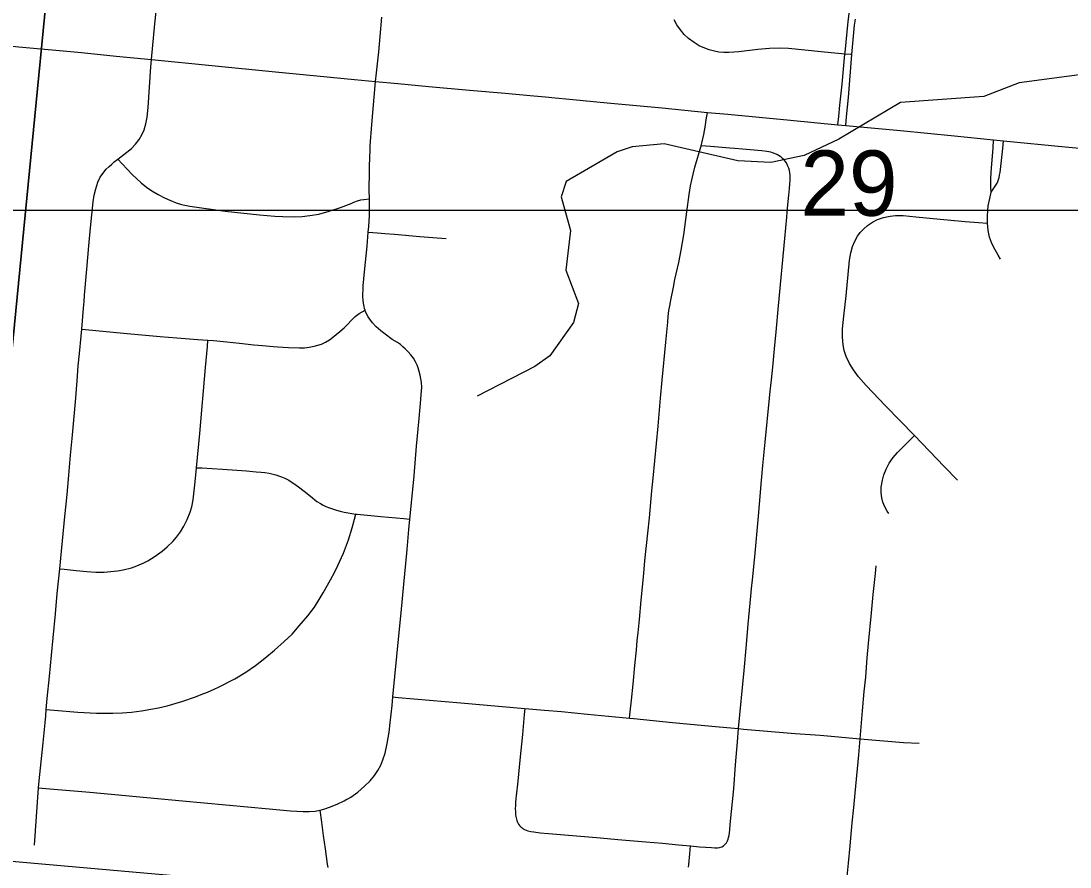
# Model space of a CAD drawing. Extents: x -1.4 to 35.4, y 0 to 22.
# Drawn here: x 27.419 to 28.091, y 13.645 to 14.188 of the extents above; entities that cross this region are included whole.
import ezdxf

# ---------------------------------------------------------------- set-up
doc = ezdxf.new("R2010")
doc.units = 0
for name, color, linetype in [('GM_X_City_Street', 7, 'Continuous'), ('GM_X_County_Road', 7, 'Continuous'), ('GM_X_County_Text', 7, 'Continuous'), ('GM_X_Minor_River', 7, 'Continuous'), ('GM_X_Section', 7, 'Continuous'), ('GM_X_Section_Text', 7, 'Continuous')]:
    doc.layers.add(name, color=color, linetype=linetype)

msp = doc.modelspace()

# ---------------------------------------------------------------- linework, layer by layer
at = {"layer": 'GM_X_City_Street'}
for points in [[(27.4274, 13.65927), (27.43003, 13.6961), (27.43034, 13.70044), (27.43287, 13.72491), (27.43414, 13.73784), (27.43456, 13.74217), (27.43492, 13.74627), (27.43553, 13.7533), (27.43691, 13.76751), (27.43827, 13.78109), (27.43931, 13.79222), (27.4408, 13.80762), (27.442, 13.8206), (27.44353, 13.8365), (27.4442, 13.84346), (27.44689, 13.87004), (27.44769, 13.87807), (27.44831, 13.88425), (27.44941, 13.89661), (27.45048, 13.90951), (27.45155, 13.92001), (27.45366, 13.94352), (27.45476, 13.9571), (27.45549, 13.96679), (27.45626, 13.97468), (27.45724, 13.98579), (27.45764, 13.99016), (27.45886, 14.00366), (27.4592, 14.00789), (27.45955, 14.01214), (27.46094, 14.02875), (27.46225, 14.04359), (27.46332, 14.05513), (27.465, 14.07198), (27.46562, 14.07618), (27.46663, 14.08032), (27.46789, 14.08446), (27.46942, 14.08762), (27.4711, 14.0901), (27.47342, 14.09289), (27.47533, 14.09456), (27.47692, 14.09604), (27.47852, 14.09746), (27.48073, 14.09918), (27.48276, 14.10073), (27.48662, 14.10367), (27.48956, 14.10607), (27.49223, 14.10884), (27.49454, 14.1119), (27.49646, 14.11523), (27.49773, 14.11817), (27.49884, 14.12183), (27.49964, 14.12619), (27.50026, 14.13243), (27.502, 14.15843), (27.50233, 14.16327), (27.50459, 14.18608), (27.50616, 14.20219)], [(27.64608, 14.14911), (27.64666, 14.15466), (27.64805, 14.1681), (27.64892, 14.17797), (27.65002, 14.19034)], [(27.94245, 14.12131), (27.94294, 14.12671), (27.9436, 14.13382), (27.94515, 14.14739), (27.94694, 14.16671), (27.94704, 14.16777), (27.94899, 14.18752), (27.94992, 14.19428)], [(27.95138, 14.1663), (27.95039, 14.16639), (27.94694, 14.16671), (27.93175, 14.16812), (27.91081, 14.17022), (27.90468, 14.17046), (27.89854, 14.17026), (27.89117, 14.1696), (27.87882, 14.16809), (27.87256, 14.16767), (27.86939, 14.16766), (27.86612, 14.16793), (27.86332, 14.16848), (27.85997, 14.16938), (27.85701, 14.1704), (27.85355, 14.17203), (27.85029, 14.17401), (27.84672, 14.17667), (27.84391, 14.17927), (27.84141, 14.18217), (27.83925, 14.18534), (27.83744, 14.18871)], [(27.94741, 14.12084), (27.94797, 14.12648), (27.9492, 14.1389), (27.95138, 14.1663), (27.95315, 14.18522), (27.95366, 14.18913)], [(27.43003, 13.6961), (27.43474, 13.69568), (27.46279, 13.6932), (27.52225, 13.68772), (27.5779, 13.68258), (27.59155, 13.68132), (27.59962, 13.68089), (27.60346, 13.68078), (27.60727, 13.68114), (27.61058, 13.68176), (27.61343, 13.68248), (27.61657, 13.68356), (27.62137, 13.68547), (27.62582, 13.68768), (27.62763, 13.68869), (27.62828, 13.68899), (27.63013, 13.69013), (27.63471, 13.69335), (27.63902, 13.69703), (27.64259, 13.70062), (27.64541, 13.70404), (27.64754, 13.7072), (27.64935, 13.71055), (27.6508, 13.71407), (27.65209, 13.7183), (27.65349, 13.72443), (27.6547, 13.73181), (27.65544, 13.73771), (27.65668, 13.7488), (27.65721, 13.75436), (27.66092, 13.79344), (27.66255, 13.80823), (27.66423, 13.82678), (27.66609, 13.84647), (27.66627, 13.84892), (27.66734, 13.86176), (27.66803, 13.86836), (27.66868, 13.87459), (27.67068, 13.89606), (27.67236, 13.91512), (27.67407, 13.93294), (27.67512, 13.94519), (27.67534, 13.94839), (27.67545, 13.95077), (27.67561, 13.95296), (27.67545, 13.95596), (27.67516, 13.95843), (27.67472, 13.9607), (27.67406, 13.96311), (27.67341, 13.96538), (27.67275, 13.9672), (27.67165, 13.96932), (27.67026, 13.97173), (27.66866, 13.97385), (27.66691, 13.97575), (27.66501, 13.97757), (27.66355, 13.97896), (27.66201, 13.98035), (27.66004, 13.98174), (27.65675, 13.98369), (27.65225, 13.98693), (27.64939, 13.98926), (27.64645, 13.99182), (27.64411, 13.99437), (27.64231, 13.99664), (27.64127, 13.99825), (27.64046, 13.99971), (27.63959, 14.00161), (27.63932, 14.00245), (27.63901, 14.00345), (27.63863, 14.00482), (27.6382, 14.00686), (27.63798, 14.00891), (27.63783, 14.01103), (27.63791, 14.01293), (27.63798, 14.01541), (27.63812, 14.01804), (27.63894, 14.02692), (27.6406, 14.04357), (27.64133, 14.05252), (27.64162, 14.05598), (27.64193, 14.05971), (27.64206, 14.06283), (27.64215, 14.07033), (27.64206, 14.07385), (27.64192, 14.07963), (27.64213, 14.09135), (27.64216, 14.09198), (27.64222, 14.09508), (27.64247, 14.10498), (27.64263, 14.10776), (27.64361, 14.12158), (27.64608, 14.14911)], [(27.80885, 13.74079), (27.80928, 13.7447), (27.81013, 13.75234), (27.81127, 13.76252), (27.81229, 13.77461), (27.81324, 13.78444), (27.81382, 13.79056), (27.8143, 13.79542), (27.81517, 13.80402), (27.81621, 13.81639), (27.81781, 13.83121), (27.8187, 13.84172), (27.82058, 13.85949), (27.82165, 13.86926), (27.82316, 13.88657), (27.82391, 13.8946), (27.82606, 13.91685), (27.82713, 13.92798), (27.8286, 13.94591), (27.82971, 13.95757), (27.83211, 13.98199), (27.83335, 13.99478), (27.83367, 13.99846), (27.83391, 14.00028), (27.83412, 14.00212), (27.83461, 14.00516), (27.83533, 14.00877), (27.83695, 14.01727), (27.8379, 14.02214), (27.84036, 14.03305), (27.84202, 14.04098), (27.84366, 14.05081), (27.84561, 14.06559), (27.84704, 14.07651), (27.84799, 14.08211), (27.84898, 14.08693), (27.85077, 14.09411), (27.8547, 14.10792), (27.85519, 14.10963), (27.85642, 14.11513), (27.85727, 14.1198), (27.85807, 14.12441), (27.85892, 14.12929)], [(28.04063, 14.07817), (28.04045, 14.08127), (28.04036, 14.0835), (28.04054, 14.08715), (28.04097, 14.0938), (28.04187, 14.10625), (28.04226, 14.11163)], [(28.04063, 14.07817), (28.04285, 14.08137), (28.04366, 14.08255), (28.04447, 14.08396), (28.04488, 14.08486), (28.0454, 14.0863), (28.04575, 14.08748), (28.0461, 14.08902), (28.04643, 14.09065), (28.0481, 14.10608), (28.04863, 14.11102)], [(27.86902, 13.65884), (27.86996, 13.65967), (27.8709, 13.66084), (27.87158, 13.66207), (27.87205, 13.66307), (27.87236, 13.66426), (27.87261, 13.66553), (27.87285, 13.6673), (27.87305, 13.66896), (27.87333, 13.67261), (27.87561, 13.69543), (27.87676, 13.71085), (27.87797, 13.7255), (27.87866, 13.73405), (27.88225, 13.77137), (27.88375, 13.78807), (27.88496, 13.80104), (27.88663, 13.81894), (27.88706, 13.82387), (27.8876, 13.82941), (27.88906, 13.84421), (27.8915, 13.87019), (27.89345, 13.8931), (27.8944, 13.90287), (27.89589, 13.91766), (27.89863, 13.94607), (27.899, 13.95039), (27.89981, 13.95781), (27.9006, 13.96583), (27.90184, 13.97752), (27.90288, 13.98855), (27.90439, 14.00521), (27.90842, 14.04845), (27.90964, 14.06203), (27.90992, 14.06511), (27.91037, 14.07005), (27.91097, 14.07622), (27.9114, 14.08053), (27.91178, 14.08605), (27.91181, 14.08775), (27.91172, 14.08905), (27.91157, 14.09058), (27.9113, 14.09199), (27.91089, 14.09356), (27.91042, 14.09481), (27.90986, 14.09595), (27.90936, 14.09686), (27.90864, 14.09791), (27.908, 14.09876), (27.90698, 14.09976), (27.90585, 14.10073), (27.90479, 14.10147), (27.90371, 14.10211), (27.90288, 14.10254), (27.90183, 14.10297), (27.90059, 14.10343), (27.89942, 14.10373), (27.89819, 14.10396), (27.89693, 14.10416), (27.89358, 14.10462), (27.88122, 14.10576), (27.87628, 14.10619), (27.87319, 14.10641), (27.86082, 14.10743), (27.8547, 14.10792)], [(27.48073, 14.09918), (27.48357, 14.09619), (27.49, 14.08939), (27.49569, 14.08406), (27.49913, 14.08135), (27.50264, 14.07894), (27.50665, 14.07653), (27.51081, 14.07449), (27.5141, 14.07303), (27.51812, 14.07135), (27.52155, 14.07025), (27.52703, 14.06908), (27.54953, 14.06587), (27.57159, 14.06361), (27.58138, 14.0628), (27.58663, 14.06251), (27.59416, 14.06236), (27.5989, 14.06258), (27.60394, 14.06309), (27.60964, 14.06404), (27.61622, 14.06587), (27.62345, 14.06817), (27.6252, 14.06885), (27.62866, 14.07024), (27.6304, 14.07091), (27.63213, 14.0716), (27.63448, 14.07252), (27.63666, 14.07318), (27.63842, 14.07339), (27.64206, 14.07385)], [(28.04658, 14.03505), (28.04526, 14.03763), (28.04215, 14.043), (28.04083, 14.04581), (28.03968, 14.04933), (28.03881, 14.05359), (28.03838, 14.05831), (28.03839, 14.06286), (28.03885, 14.06936), (28.03974, 14.07408), (28.04063, 14.07817)], [(28.01919, 13.89331), (28.01049, 13.90217), (27.99154, 13.92207), (27.97302, 13.94114), (27.96054, 13.9541), (27.95566, 13.95966), (27.95233, 13.96407), (27.94978, 13.96822), (27.94775, 13.97261), (27.94644, 13.97665), (27.94575, 13.98021), (27.94529, 13.98505), (27.94542, 13.99055), (27.9463, 13.99856), (27.94762, 14.01156), (27.94985, 14.03443), (27.95067, 14.03924), (27.95182, 14.04332), (27.95319, 14.04668), (27.95497, 14.04982), (27.95674, 14.05224), (27.95875, 14.05447), (27.96148, 14.05683), (27.9645, 14.05882), (27.96773, 14.06047), (27.97169, 14.06193), (27.97582, 14.06281), (27.97943, 14.06314), (27.98432, 14.06309), (27.99232, 14.0623), (28.00348, 14.06129), (28.0239, 14.0593), (28.03263, 14.0587), (28.03838, 14.05831)], [(27.64133, 14.05252), (27.64719, 14.05201), (27.65205, 14.0516), (27.65816, 14.05111), (27.67431, 14.04974), (27.68273, 14.04902), (27.69121, 14.04843)], [(27.45764, 13.99016), (27.46002, 13.98993), (27.48449, 13.98765), (27.49376, 13.98682), (27.508, 13.98561), (27.51853, 13.98477), (27.53214, 13.98371), (27.5386, 13.98317), (27.54204, 13.98287), (27.5507, 13.98207), (27.55874, 13.98128), (27.568, 13.98028), (27.57356, 13.97976), (27.58036, 13.97919), (27.58341, 13.97891), (27.5902, 13.9784), (27.59719, 13.97817), (27.60048, 13.97832), (27.60355, 13.97868), (27.60661, 13.97927), (27.60902, 13.97996), (27.61131, 13.98064), (27.61395, 13.98195), (27.61648, 13.98347), (27.61843, 13.9849), (27.62085, 13.98676), (27.62319, 13.98872), (27.62585, 13.99118), (27.62805, 13.99331), (27.63068, 13.99593), (27.63291, 13.99826), (27.63553, 14.00023), (27.63932, 14.00245)], [(27.44353, 13.8365), (27.44636, 13.83624), (27.45415, 13.8355), (27.46097, 13.83484), (27.46674, 13.83448), (27.472, 13.83445), (27.47626, 13.83473), (27.48051, 13.83529), (27.48414, 13.83594), (27.48951, 13.83721), (27.49296, 13.83835), (27.49742, 13.84032), (27.50011, 13.84174), (27.50481, 13.84461), (27.50927, 13.84784), (27.51251, 13.85063), (27.51599, 13.85406), (27.51837, 13.85683), (27.52095, 13.86025), (27.52317, 13.86387), (27.52533, 13.86826), (27.52713, 13.8728), (27.52815, 13.8763), (27.52904, 13.88072), (27.53016, 13.89031), (27.53081, 13.89653), (27.53129, 13.9014), (27.53342, 13.9233), (27.53708, 13.96567), (27.53825, 13.97911), (27.5386, 13.98317)], [(27.97509, 13.87203), (27.97402, 13.87356), (27.97247, 13.87626), (27.9712, 13.87922), (27.97051, 13.88215), (27.97017, 13.88524), (27.97025, 13.88898), (27.97091, 13.8933), (27.97191, 13.8969), (27.97327, 13.90038), (27.97534, 13.90423), (27.97781, 13.90782), (27.98062, 13.91116), (27.98813, 13.91866), (27.99154, 13.92207)], [(27.53129, 13.9014), (27.5346, 13.90119), (27.5479, 13.90034), (27.56334, 13.89933), (27.56949, 13.89876), (27.57268, 13.89853), (27.57503, 13.89828), (27.57784, 13.89788), (27.58039, 13.89728), (27.58205, 13.89682), (27.58387, 13.89625), (27.58577, 13.89557), (27.58781, 13.89468), (27.58912, 13.89399), (27.59048, 13.89328), (27.59197, 13.89233), (27.59357, 13.89132), (27.5951, 13.89024), (27.59657, 13.88919), (27.60026, 13.88627), (27.60433, 13.88305), (27.60844, 13.87977), (27.61065, 13.87832), (27.6124, 13.87731), (27.61416, 13.87646), (27.61646, 13.87556), (27.61852, 13.8749), (27.62091, 13.87415), (27.62334, 13.87344), (27.62585, 13.8728), (27.62841, 13.87234), (27.63081, 13.87194), (27.63348, 13.87161), (27.63421, 13.87151), (27.64942, 13.87017), (27.66422, 13.86873), (27.66803, 13.86836)], [(27.43492, 13.74627), (27.43994, 13.7458), (27.45524, 13.7446), (27.4671, 13.74391), (27.47264, 13.74393), (27.4776, 13.74391), (27.48366, 13.7442), (27.48951, 13.74467), (27.49589, 13.74554), (27.50206, 13.74649), (27.50695, 13.74746), (27.51234, 13.7487), (27.52189, 13.75139), (27.53058, 13.75441), (27.53423, 13.75583), (27.53828, 13.75743), (27.54256, 13.75935), (27.54537, 13.76062), (27.55581, 13.76597), (27.56293, 13.7702), (27.56912, 13.77457), (27.57509, 13.77913), (27.58134, 13.78444), (27.58752, 13.78995), (27.5925, 13.79469), (27.59706, 13.79989), (27.60264, 13.80641), (27.6068, 13.81192), (27.60989, 13.81689), (27.61246, 13.82117), (27.61708, 13.82939), (27.6199, 13.83463), (27.62192, 13.83866), (27.62541, 13.84658), (27.6287, 13.85518), (27.63112, 13.86284), (27.6326, 13.86835), (27.63348, 13.87161)], [(27.94841, 13.63913), (27.9492, 13.64776), (27.9502, 13.65885), (27.95163, 13.6736), (27.95261, 13.68343), (27.95353, 13.69265), (27.95583, 13.71729), (27.95674, 13.72743), (27.95819, 13.74553), (27.95934, 13.75788), (27.96023, 13.76713), (27.96123, 13.77945), (27.96201, 13.78869), (27.96388, 13.80838), (27.96507, 13.82001), (27.96649, 13.83355), (27.96705, 13.83844)], [(27.65721, 13.75436), (27.66062, 13.75407), (27.70071, 13.75066), (27.74166, 13.74698), (27.75423, 13.74585), (27.76516, 13.74495), (27.782, 13.74335), (27.80885, 13.74079), (27.81156, 13.74054), (27.83642, 13.73803), (27.86639, 13.73523), (27.87866, 13.73405), (27.88183, 13.73372), (27.9151, 13.73091), (27.93114, 13.72981), (27.95674, 13.72743), (27.98446, 13.7252), (27.99448, 13.7246)], [(27.74166, 13.74698), (27.74133, 13.74318), (27.74022, 13.73016), (27.73862, 13.7137), (27.73728, 13.70026), (27.73619, 13.69102), (27.73602, 13.68912), (27.73582, 13.68687), (27.73572, 13.68472), (27.73561, 13.68248), (27.73567, 13.68091), (27.73582, 13.6789), (27.73602, 13.67759), (27.73632, 13.67605), (27.73655, 13.6752), (27.73685, 13.67449), (27.73718, 13.67362), (27.73773, 13.6727), (27.73836, 13.67183)], [(27.61574, 13.64489), (27.61526, 13.64718), (27.61387, 13.65692), (27.6127, 13.66546), (27.61158, 13.67408), (27.61058, 13.68176)], [(27.73836, 13.67183), (27.73928, 13.6709), (27.73992, 13.67032), (27.74065, 13.66983), (27.74145, 13.66935), (27.74256, 13.66885), (27.74368, 13.66851), (27.74563, 13.66807), (27.74749, 13.66778), (27.75159, 13.66724), (27.75697, 13.66668), (27.77485, 13.6652), (27.79033, 13.66396), (27.80143, 13.66282), (27.81927, 13.66143), (27.82987, 13.6605), (27.84023, 13.65943), (27.84789, 13.65879), (27.85375, 13.65831), (27.86136, 13.65772), (27.86361, 13.65759), (27.86514, 13.65759), (27.8666, 13.65777), (27.86794, 13.65826), (27.86902, 13.65884)], [(27.84669, 13.6451), (27.84685, 13.64695), (27.84744, 13.6537), (27.84789, 13.65879)]]:
    msp.add_lwpolyline(points, dxfattribs=at)
at = {"layer": 'GM_X_County_Road'}
for points in [[(27.28916, 14.18319), (27.3029, 14.18182), (27.32709, 14.17981), (27.35495, 14.17795), (27.37159, 14.17624), (27.39259, 14.17388), (27.41733, 14.17135), (27.45754, 14.16763), (27.47979, 14.16541), (27.50233, 14.16327)], [(27.50233, 14.16327), (27.54099, 14.15932), (27.58182, 14.15532), (27.6084, 14.15277), (27.63253, 14.15043), (27.64608, 14.14911)], [(27.64608, 14.14911), (27.66035, 14.14773), (27.68015, 14.14577), (27.70615, 14.14354), (27.72906, 14.14156), (27.74513, 14.14015), (27.75251, 14.13942), (27.75495, 14.13918), (27.76109, 14.13856), (27.77035, 14.13767), (27.79447, 14.13544), (27.82971, 14.13209), (27.85892, 14.12929)], [(27.85892, 14.12929), (27.87177, 14.12807), (27.91198, 14.12435), (27.94245, 14.12131)], [(27.94245, 14.12131), (27.94741, 14.12084), (27.96142, 14.1195), (27.98246, 14.11757), (28.01707, 14.11421), (28.04226, 14.11163)], [(28.04226, 14.11163), (28.04863, 14.11102), (28.08821, 14.10725), (28.10672, 14.10547), (28.13669, 14.10257), (28.1604, 14.10074), (28.1833, 14.09862), (28.20373, 14.09672), (28.23097, 14.09433), (28.24766, 14.0927), (28.27176, 14.09022), (28.28227, 14.08926), (28.30018, 14.08754), (28.32552, 14.08509), (28.34407, 14.08341), (28.36932, 14.08085)]]:
    msp.add_lwpolyline(points, dxfattribs=at)
msp.add_lwpolyline([(27.33112, 13.05458), (28.37374, 13.05458), (28.42239, 13.55975), (27.3811, 13.65162)], close=True, dxfattribs=at)
at = {"layer": 'GM_X_County_Text'}
msp.add_lwpolyline([(24.48967, 15.27515), (24.48967, 14.06648), (28.48645, 14.06648)], dxfattribs=at)
at = {"layer": 'GM_X_Minor_River'}
msp.add_lwpolyline([(28.11984, 14.15641), (28.0586, 14.14816), (28.03605, 14.13951), (27.98248, 14.13566), (27.94294, 14.11217), (27.92073, 14.10161), (27.89939, 14.09711), (27.87817, 14.0983), (27.83097, 14.10913), (27.81045, 14.10727), (27.8009, 14.10404), (27.76828, 14.08497), (27.76505, 14.07517), (27.77106, 14.05341), (27.7679, 14.02804), (27.77619, 14.00662), (27.77292, 13.99454), (27.75769, 13.97321), (27.74807, 13.96619), (27.71127, 13.9472)], dxfattribs=at)
at = {"layer": 'GM_X_Section'}
for points in [[(27.48098, 14.67461), (27.3811, 13.65162), (26.39247, 13.74598), (26.47381, 14.7481)], [(28.5233, 14.5759), (28.42239, 13.55975), (27.3811, 13.65162), (27.48098, 14.67461)]]:
    msp.add_lwpolyline(points, close=True, dxfattribs=at)

# ---------------------------------------------------------------- texts
at = {"layer": 'GM_X_Section_Text'}
msp.add_text('29', height=0.041856, rotation=0.00001, dxfattribs=at).set_placement((27.91839, 14.06298))

doc.saveas('drawing.dxf')
